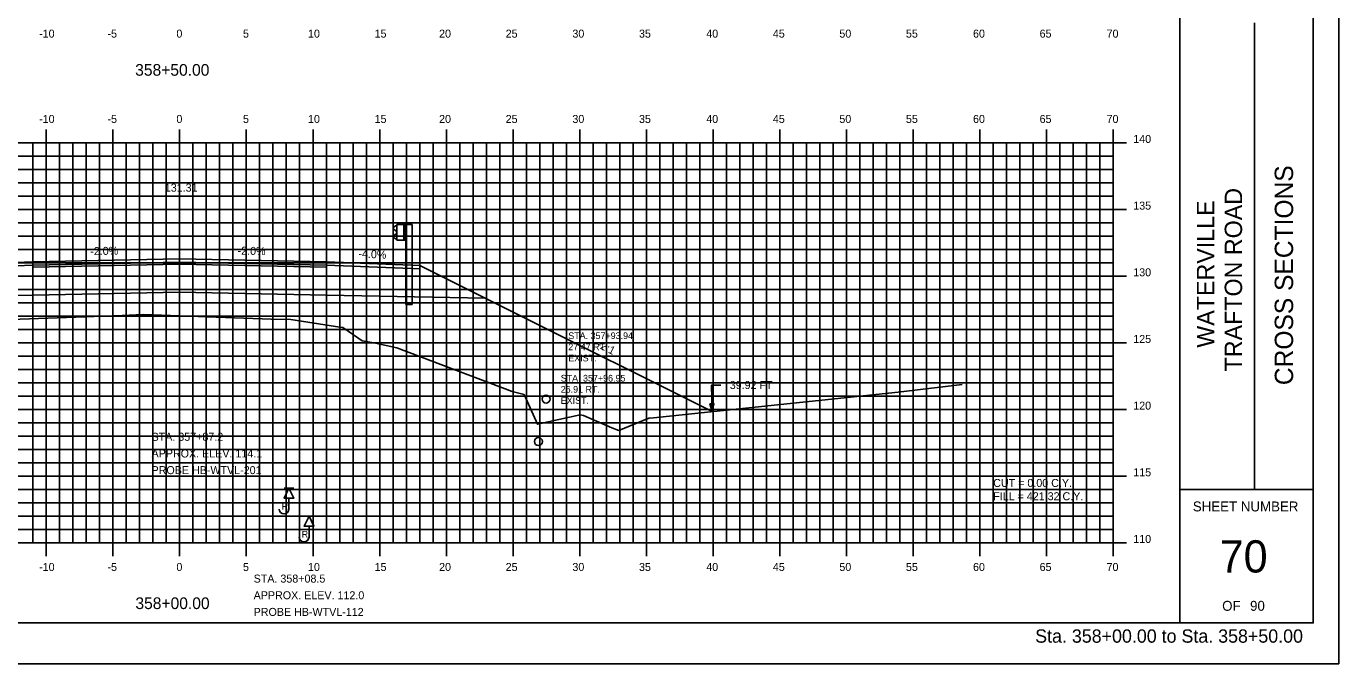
# Model space of a CAD drawing. Extents: x 1146081 to 1146251, y 608981 to 609091.
# Drawn here: x 1146152.7 to 1146251.1, y 608981.3 to 609029.1 of the extents above; entities that cross this region are included whole.
import ezdxf

# ---------------------------------------------------------------- set-up
doc = ezdxf.new("R2010")
doc.units = 0
for name, color, linetype in [('ANNOTATION', 7, 'Continuous'), ('BORDER', 7, 'Continuous'), ('D_Guardrail_Beam_Rt', 7, 'Continuous'), ('D_Guardrail_ConcBarrier', 7, 'Continuous'), ('D_Roadway_Centerline', 7, 'Continuous'), ('D_Roadway_Centerline_Text', 7, 'Continuous'), ('D_Roadway_Edge_Shoulder', 7, 'Continuous'), ('D_Roadway_Edge_TW', 7, 'Continuous'), ('D_Roadway_Pavement', 7, 'Continuous'), ('D_Roadway_SlopeLines', 7, 'Continuous'), ('D_Roadway_SubGrade', 7, 'Continuous'), ('D_Text_Monospaced', 7, 'Continuous'), ('D_Text_Standard', 7, 'Continuous'), ('H_V ANNOTATION', 7, 'Continuous'), ('HIGHWAY_TITLE', 7, 'Continuous'), ('MAJOR', 7, 'Continuous'), ('MINOR', 7, 'Continuous'), ('PLOT BOUNDARY', 7, 'Continuous'), ('ROCKS', 7, 'Continuous'), ('S_Drainage_Invert', 7, 'Continuous'), ('S_Roadway_Centerline', 7, 'Continuous')]:
    doc.layers.add(name, color=color, linetype=linetype)

msp = doc.modelspace()

# ---------------------------------------------------------------- linework, layer by layer
msp.add_lwpolyline([(1146119.749, 608997.946), (1146139.24, 609007.691), (1146141.24, 609008.691), (1146146.157, 609011.15), (1146146.158, 609011.15), (1146153.158, 609011.43), (1146164.158, 609011.65), (1146175.158, 609011.43), (1146182.158, 609011.15), (1146187.075, 609008.692), (1146189.075, 609007.692), (1146204.079, 609000.19)])
at = {"layer": 'BORDER'}
for p, q in [((1146239.158, 608984.335), (1146239.158, 609089.335)), ((1146244.749, 608994.338), (1146244.749, 609029.338)), ((1146239.158, 608994.338), (1146249.158, 608994.338))]:
    msp.add_line(p, q, dxfattribs=at)
msp.add_lwpolyline([(1146089.158, 608984.335), (1146249.158, 608984.335), (1146249.158, 609089.335), (1146089.158, 609089.335)], close=True, dxfattribs=at)
at = {"layer": 'D_Guardrail_Beam_Rt'}
for p, q in [((1146180.35, 609014.11), (1146180.207, 609014.01)), ((1146180.207, 609013.867), (1146180.402, 609013.731)), ((1146180.402, 609013.532), (1146180.207, 609013.396)), ((1146180.44, 609014.131), (1146180.366, 609014.117)), ((1146180.436, 609013.666), (1146180.436, 609013.596)), ((1146180.207, 609013.252), (1146180.35, 609013.152)), ((1146180.366, 609013.146), (1146180.44, 609013.131))]:
    msp.add_line(p, q, dxfattribs=at)
for centre, major_axis, start_param, end_param in [((1146180.257, 609013.938), (-0.0877, 0), 5.323254, 7.243116), ((1146180.374, 609014.076), (-0.0417, 0), 4.907132, 5.323254), ((1146180.357, 609013.666), (0.0789, 0), 0, 0.959931), ((1146180.357, 609013.596), (0.0789, 0), 5.323254, 6.283185), ((1146180.257, 609013.324), (-0.0877, 0), 5.323254, 7.243116), ((1146180.374, 609013.186), (-0.0417, 0), 0.959931, 1.376053)]:
    msp.add_ellipse(centre, major_axis=major_axis, ratio=0.995501, start_param=start_param, end_param=end_param, dxfattribs=at)
at = {"layer": 'D_Guardrail_ConcBarrier'}
for p, q in [((1146180.44, 609014.215), (1146181.127, 609014.215)), ((1146180.44, 609013.048), (1146180.44, 609014.215)), ((1146180.961, 609014.215), (1146180.961, 609013.048)), ((1146181.065, 609014.215), (1146181.065, 609013.048)), ((1146181.127, 609014.215), (1146181.598, 609014.215)), ((1146181.127, 609014.215), (1146181.127, 609013.048)), ((1146181.598, 609014.215), (1146181.598, 609008.215)), ((1146181.127, 609013.048), (1146180.44, 609013.048)), ((1146181.107, 609008.215), (1146181.107, 609013.048)), ((1146181.107, 609008.215), (1146181.598, 609008.215))]:
    msp.add_line(p, q, dxfattribs=at)
at = {"layer": 'D_Roadway_Edge_Shoulder'}
for points in [[(1146153.158, 609011.43), (1146146.158, 609011.15), (1146146.158, 609010.9), (1146153.158, 609011.18)], [(1146175.158, 609011.43), (1146182.158, 609011.15), (1146182.158, 609010.9), (1146175.158, 609011.18)]]:
    msp.add_lwpolyline(points, close=True, dxfattribs=at)
at = {"layer": 'D_Roadway_Edge_TW'}
msp.add_lwpolyline([(1146153.158, 609011.18), (1146153.158, 609011.43), (1146164.158, 609011.65), (1146175.158, 609011.43), (1146175.158, 609011.18), (1146164.158, 609011.4)], close=True, dxfattribs=at)
at = {"layer": 'D_Roadway_Pavement'}
msp.add_lwpolyline([(1146153.158, 609011.013), (1146153.158, 609011.18), (1146164.158, 609011.4), (1146175.158, 609011.18), (1146175.158, 609011.013), (1146164.158, 609011.233)], close=True, dxfattribs=at)
at = {"layer": 'D_Roadway_SlopeLines'}
for points in [[(1146187.075, 609008.692), (1146189.075, 609007.692)], [(1146189.075, 609007.692), (1146204.079, 609000.19)]]:
    msp.add_lwpolyline(points, dxfattribs=at)
at = {"layer": 'D_Roadway_SubGrade'}
for points in [[(1146153.158, 609011.013), (1146153.158, 609011.18), (1146146.158, 609010.9), (1146146.158, 609011.15), (1146146.157, 609011.15), (1146141.24, 609008.691), (1146153.158, 609008.93)], [(1146153.158, 609008.93), (1146153.158, 609011.013), (1146164.158, 609011.233), (1146175.158, 609011.013), (1146175.158, 609008.93), (1146164.158, 609009.15)], [(1146175.158, 609011.013), (1146175.158, 609011.18), (1146182.158, 609010.9), (1146182.158, 609011.15), (1146182.158, 609011.15), (1146187.075, 609008.692), (1146175.158, 609008.93)]]:
    msp.add_lwpolyline(points, close=True, dxfattribs=at)
at = {"layer": 'D_Text_Standard'}
msp.add_lwpolyline([(1146204.079, 609000.19), (1146204.045, 609002.18), (1146204.725, 609002.18)], dxfattribs=at)
msp.add_lwpolyline([(1146204.079, 609000.19), (1146203.923, 609000.769), (1146204.214, 609000.774)], close=True, dxfattribs=at)
at = {"layer": 'MAJOR'}
for p, q in [((1146154.158, 609021.337), (1146154.158, 609020.335)), ((1146159.158, 609021.337), (1146159.158, 609020.335)), ((1146164.158, 609021.337), (1146164.158, 609020.335)), ((1146169.158, 609021.337), (1146169.158, 609020.335)), ((1146174.158, 609021.337), (1146174.158, 609020.335)), ((1146179.158, 609021.337), (1146179.158, 609020.335)), ((1146184.158, 609021.337), (1146184.158, 609020.335)), ((1146189.158, 609021.337), (1146189.158, 609020.335)), ((1146194.158, 609021.337), (1146194.158, 609020.335)), ((1146199.158, 609021.337), (1146199.158, 609020.335)), ((1146204.158, 609021.337), (1146204.158, 609020.335)), ((1146209.158, 609021.337), (1146209.158, 609020.335)), ((1146214.158, 609021.337), (1146214.158, 609020.335)), ((1146219.158, 609021.337), (1146219.158, 609020.335)), ((1146224.158, 609021.337), (1146224.158, 609020.335)), ((1146229.158, 609021.337), (1146229.158, 609020.335)), ((1146234.158, 609021.337), (1146234.158, 609020.335)), ((1146094.158, 609020.335), (1146234.158, 609020.335)), ((1146094.158, 609020.335), (1146234.158, 609020.335)), ((1146154.158, 608990.335), (1146154.158, 609020.335)), ((1146159.158, 608990.335), (1146159.158, 609020.335)), ((1146164.158, 608990.335), (1146164.158, 609020.335)), ((1146169.158, 608990.335), (1146169.158, 609020.335)), ((1146174.158, 608990.335), (1146174.158, 609020.335)), ((1146179.158, 608990.335), (1146179.158, 609020.335)), ((1146184.158, 608990.335), (1146184.158, 609020.335)), ((1146189.158, 608990.335), (1146189.158, 609020.335)), ((1146194.158, 608990.335), (1146194.158, 609020.335)), ((1146199.158, 608990.335), (1146199.158, 609020.335)), ((1146204.158, 608990.335), (1146204.158, 609020.335)), ((1146209.158, 608990.335), (1146209.158, 609020.335)), ((1146214.158, 608990.335), (1146214.158, 609020.335)), ((1146219.158, 608990.335), (1146219.158, 609020.335)), ((1146224.158, 608990.335), (1146224.158, 609020.335)), ((1146229.158, 608990.335), (1146229.158, 609020.335)), ((1146235.16, 609020.335), (1146233.156, 609020.335)), ((1146234.158, 608990.335), (1146234.158, 609020.335)), ((1146234.158, 608990.335), (1146234.158, 609020.335)), ((1146094.158, 609015.335), (1146234.158, 609015.335)), ((1146235.16, 609015.335), (1146233.156, 609015.335)), ((1146094.158, 609010.335), (1146234.158, 609010.335)), ((1146235.16, 609010.335), (1146233.156, 609010.335)), ((1146094.158, 609005.335), (1146234.158, 609005.335)), ((1146235.16, 609005.335), (1146233.156, 609005.335)), ((1146094.158, 609000.335), (1146234.158, 609000.335)), ((1146235.16, 609000.335), (1146233.156, 609000.335)), ((1146094.158, 608995.335), (1146234.158, 608995.335)), ((1146235.16, 608995.335), (1146233.156, 608995.335)), ((1146094.158, 608990.335), (1146234.158, 608990.335)), ((1146094.158, 608990.335), (1146234.158, 608990.335)), ((1146154.158, 608989.333), (1146154.158, 608990.335)), ((1146159.158, 608989.333), (1146159.158, 608990.335)), ((1146164.158, 608989.333), (1146164.158, 608990.335)), ((1146169.158, 608989.333), (1146169.158, 608990.335)), ((1146174.158, 608989.333), (1146174.158, 608990.335)), ((1146179.158, 608989.333), (1146179.158, 608990.335)), ((1146184.158, 608989.333), (1146184.158, 608990.335)), ((1146189.158, 608989.333), (1146189.158, 608990.335)), ((1146194.158, 608989.333), (1146194.158, 608990.335)), ((1146199.158, 608989.333), (1146199.158, 608990.335)), ((1146204.158, 608989.333), (1146204.158, 608990.335)), ((1146209.158, 608989.333), (1146209.158, 608990.335)), ((1146214.158, 608989.333), (1146214.158, 608990.335)), ((1146219.158, 608989.333), (1146219.158, 608990.335)), ((1146224.158, 608989.333), (1146224.158, 608990.335)), ((1146229.158, 608989.333), (1146229.158, 608990.335)), ((1146235.16, 608990.335), (1146233.156, 608990.335)), ((1146234.158, 608989.333), (1146234.158, 608990.335))]:
    msp.add_line(p, q, dxfattribs=at)
at = {"layer": 'MINOR'}
for p, q in [((1146153.158, 608990.335), (1146153.158, 609020.335)), ((1146155.158, 608990.335), (1146155.158, 609020.335)), ((1146156.158, 608990.335), (1146156.158, 609020.335)), ((1146157.158, 608990.335), (1146157.158, 609020.335)), ((1146158.158, 608990.335), (1146158.158, 609020.335)), ((1146160.158, 608990.335), (1146160.158, 609020.335)), ((1146161.158, 608990.335), (1146161.158, 609020.335)), ((1146162.158, 608990.335), (1146162.158, 609020.335)), ((1146163.158, 608990.335), (1146163.158, 609020.335)), ((1146165.158, 608990.335), (1146165.158, 609020.335)), ((1146166.158, 608990.335), (1146166.158, 609020.335)), ((1146167.158, 608990.335), (1146167.158, 609020.335)), ((1146168.158, 608990.335), (1146168.158, 609020.335)), ((1146170.158, 608990.335), (1146170.158, 609020.335)), ((1146171.158, 608990.335), (1146171.158, 609020.335)), ((1146172.158, 608990.335), (1146172.158, 609020.335)), ((1146173.158, 608990.335), (1146173.158, 609020.335)), ((1146175.158, 608990.335), (1146175.158, 609020.335)), ((1146176.158, 608990.335), (1146176.158, 609020.335)), ((1146177.158, 608990.335), (1146177.158, 609020.335)), ((1146178.158, 608990.335), (1146178.158, 609020.335)), ((1146180.158, 608990.335), (1146180.158, 609020.335)), ((1146181.158, 608990.335), (1146181.158, 609020.335)), ((1146182.158, 608990.335), (1146182.158, 609020.335)), ((1146183.158, 608990.335), (1146183.158, 609020.335)), ((1146185.158, 608990.335), (1146185.158, 609020.335)), ((1146186.158, 608990.335), (1146186.158, 609020.335)), ((1146187.158, 608990.335), (1146187.158, 609020.335)), ((1146188.158, 608990.335), (1146188.158, 609020.335)), ((1146190.158, 608990.335), (1146190.158, 609020.335)), ((1146191.158, 608990.335), (1146191.158, 609020.335)), ((1146192.158, 608990.335), (1146192.158, 609020.335)), ((1146193.158, 608990.335), (1146193.158, 609020.335)), ((1146195.158, 608990.335), (1146195.158, 609020.335)), ((1146196.158, 608990.335), (1146196.158, 609020.335)), ((1146197.158, 608990.335), (1146197.158, 609020.335)), ((1146198.158, 608990.335), (1146198.158, 609020.335)), ((1146200.158, 608990.335), (1146200.158, 609020.335)), ((1146201.158, 608990.335), (1146201.158, 609020.335)), ((1146202.158, 608990.335), (1146202.158, 609020.335)), ((1146203.158, 608990.335), (1146203.158, 609020.335)), ((1146205.158, 608990.335), (1146205.158, 609020.335)), ((1146206.158, 608990.335), (1146206.158, 609020.335)), ((1146207.158, 608990.335), (1146207.158, 609020.335)), ((1146208.158, 608990.335), (1146208.158, 609020.335)), ((1146210.158, 608990.335), (1146210.158, 609020.335)), ((1146211.158, 608990.335), (1146211.158, 609020.335)), ((1146212.158, 608990.335), (1146212.158, 609020.335)), ((1146213.158, 608990.335), (1146213.158, 609020.335)), ((1146215.158, 608990.335), (1146215.158, 609020.335)), ((1146216.158, 608990.335), (1146216.158, 609020.335)), ((1146217.158, 608990.335), (1146217.158, 609020.335)), ((1146218.158, 608990.335), (1146218.158, 609020.335)), ((1146220.158, 608990.335), (1146220.158, 609020.335)), ((1146221.158, 608990.335), (1146221.158, 609020.335)), ((1146222.158, 608990.335), (1146222.158, 609020.335)), ((1146223.158, 608990.335), (1146223.158, 609020.335)), ((1146225.158, 608990.335), (1146225.158, 609020.335)), ((1146226.158, 608990.335), (1146226.158, 609020.335)), ((1146227.158, 608990.335), (1146227.158, 609020.335)), ((1146228.158, 608990.335), (1146228.158, 609020.335)), ((1146230.158, 608990.335), (1146230.158, 609020.335)), ((1146231.158, 608990.335), (1146231.158, 609020.335)), ((1146232.158, 608990.335), (1146232.158, 609020.335)), ((1146233.158, 608990.335), (1146233.158, 609020.335)), ((1146094.158, 609019.335), (1146234.158, 609019.335)), ((1146234.158, 609019.335), (1146233.156, 609019.335)), ((1146094.158, 609018.335), (1146234.158, 609018.335)), ((1146234.158, 609018.335), (1146233.156, 609018.335)), ((1146094.158, 609017.335), (1146234.158, 609017.335)), ((1146234.158, 609017.335), (1146233.156, 609017.335)), ((1146094.158, 609016.335), (1146234.158, 609016.335)), ((1146234.158, 609016.335), (1146233.156, 609016.335)), ((1146094.158, 609014.335), (1146234.158, 609014.335)), ((1146234.158, 609014.335), (1146233.156, 609014.335)), ((1146094.158, 609013.335), (1146234.158, 609013.335)), ((1146234.158, 609013.335), (1146233.156, 609013.335)), ((1146094.158, 609012.335), (1146234.158, 609012.335)), ((1146234.158, 609012.335), (1146233.156, 609012.335)), ((1146094.158, 609011.335), (1146234.158, 609011.335)), ((1146234.158, 609011.335), (1146233.156, 609011.335)), ((1146094.158, 609009.335), (1146234.158, 609009.335)), ((1146234.158, 609009.335), (1146233.156, 609009.335)), ((1146094.158, 609008.335), (1146234.158, 609008.335)), ((1146234.158, 609008.335), (1146233.156, 609008.335)), ((1146094.158, 609007.335), (1146234.158, 609007.335)), ((1146234.158, 609007.335), (1146233.156, 609007.335)), ((1146094.158, 609006.335), (1146234.158, 609006.335)), ((1146234.158, 609006.335), (1146233.156, 609006.335)), ((1146094.158, 609004.335), (1146234.158, 609004.335)), ((1146234.158, 609004.335), (1146233.156, 609004.335)), ((1146094.158, 609003.335), (1146234.158, 609003.335)), ((1146234.158, 609003.335), (1146233.156, 609003.335)), ((1146094.158, 609002.335), (1146234.158, 609002.335)), ((1146234.158, 609002.335), (1146233.156, 609002.335)), ((1146094.158, 609001.335), (1146234.158, 609001.335)), ((1146234.158, 609001.335), (1146233.156, 609001.335)), ((1146094.158, 608999.335), (1146234.158, 608999.335)), ((1146234.158, 608999.335), (1146233.156, 608999.335)), ((1146094.158, 608998.335), (1146234.158, 608998.335)), ((1146234.158, 608998.335), (1146233.156, 608998.335)), ((1146094.158, 608997.335), (1146234.158, 608997.335)), ((1146234.158, 608997.335), (1146233.156, 608997.335)), ((1146094.158, 608996.335), (1146234.158, 608996.335)), ((1146234.158, 608996.335), (1146233.156, 608996.335)), ((1146094.158, 608994.335), (1146234.158, 608994.335)), ((1146234.158, 608994.335), (1146233.156, 608994.335)), ((1146094.158, 608993.335), (1146234.158, 608993.335)), ((1146234.158, 608993.335), (1146233.156, 608993.335)), ((1146094.158, 608992.335), (1146234.158, 608992.335)), ((1146234.158, 608992.335), (1146233.156, 608992.335)), ((1146094.158, 608991.335), (1146234.158, 608991.335)), ((1146234.158, 608991.335), (1146233.156, 608991.335))]:
    msp.add_line(p, q, dxfattribs=at)
at = {"layer": 'PLOT BOUNDARY'}
msp.add_lwpolyline([(1146081.065, 608981.276), (1146251.065, 608981.276), (1146251.065, 609091.276), (1146081.065, 609091.276)], close=True, dxfattribs=at)
at = {"layer": 'ROCKS'}
for p, q in [((1146172.727, 608994.435), (1146171.989, 608994.435)), ((1146172.358, 608993.697), (1146172.358, 608992.882)), ((1146174.227, 608992.335), (1146173.489, 608992.335)), ((1146173.858, 608991.597), (1146173.858, 608990.782))]:
    msp.add_line(p, q, dxfattribs=at)
for points in [[(1146172.358, 608994.435), (1146172.727, 608993.697), (1146171.989, 608993.697)], [(1146173.858, 608992.335), (1146174.227, 608991.597), (1146173.489, 608991.597)]]:
    msp.add_lwpolyline(points, close=True, dxfattribs=at)
for centre in [(1146171.985, 608992.882), (1146173.485, 608990.782)]:
    msp.add_arc(centre, 0.373, 180, 0, dxfattribs=at)
at = {"layer": 'S_Drainage_Invert'}
for centre in [(1146191.632, 609001.129), (1146191.064, 608997.944)]:
    msp.add_circle(centre, 0.3, dxfattribs=at)
at = {"layer": 'S_Roadway_Centerline'}
msp.add_lwpolyline([(1146150.798, 609007.066), (1146159.846, 609007.401), (1146161.432, 609007.464), (1146171.01, 609007.121), (1146172.487, 609007.085), (1146175.847, 609006.568), (1146176.385, 609006.506), (1146177.841, 609005.488), (1146178.841, 609005.331), (1146180.447, 609004.962), (1146189.096, 609001.7), (1146189.983, 609001.469), (1146191.002, 608999.24), (1146194.178, 608999.938), (1146194.441, 608999.898), (1146196.553, 608998.968), (1146197.09, 608998.777), (1146199.348, 608999.689), (1146199.382, 608999.703), (1146199.69, 608999.732), (1146218.043, 609001.646), (1146222.835, 609002.21)], dxfattribs=at)

# ---------------------------------------------------------------- texts
at = {"layer": 'ANNOTATION'}
for s, rotation, p in [('-2.0%', 1.14576, (1146157.461, 609011.916)), ('-2.0%', 358.85424, (1146168.501, 609011.963)), ('-4.0%', 357.70939, (1146177.554, 609011.735)), ('-2:1', 333.43495, (1146195.4, 609005.047))]:
    msp.add_text(s, height=0.6, rotation=rotation, dxfattribs=at).set_placement(p)
at = {"layer": 'BORDER'}
msp.add_text('CROSS SECTIONS', height=1.37787, rotation=90, dxfattribs=at).set_placement((1146247.643, 609002.172))
for s, height, p in [('SHEET NUMBER', 0.74527, (1146240.124, 608992.701)), ('70', 2.4194, (1146242.134, 608988.118)), ('OF', 0.7453, (1146242.325, 608985.248)), ('90', 0.7453, (1146244.415, 608985.248))]:
    msp.add_text(s, height=height, dxfattribs=at).set_placement(p)
at = {"layer": 'D_Roadway_Centerline'}
for s, p in [('C', (1146164.153, 609011.65)), ('L', (1146164.158, 609011.643))]:
    msp.add_text(s, height=0.0146, dxfattribs=at).set_placement(p)
at = {"layer": 'D_Roadway_Centerline_Text'}
msp.add_text('131.31', height=0.6, dxfattribs=at).set_placement((1146163.045, 609016.682))
at = {"layer": 'D_Text_Monospaced'}
for s, height, p in [('STA. 357+93.94', 0.49998, (1146193.299, 609005.627)), ('27.47 RT.', 0.5, (1146193.299, 609004.793)), ('EXIST. ', 0.5, (1146193.299, 609003.953)), ('STA. 357+96.95', 0.49998, (1146192.731, 609002.442)), ('26.91 RT.', 0.5, (1146192.731, 609001.608)), ('EXIST. ', 0.5, (1146192.731, 609000.768))]:
    msp.add_text(s, height=height, dxfattribs=at).set_placement(p)
at = {"layer": 'D_Text_Standard'}
for s, p in [('39.92 FT', (1146205.405, 609001.88)), ('CUT = 0.00 C.Y.', (1146225.158, 608994.535)), ('FILL = 421.32 C.Y.', (1146225.158, 608993.539))]:
    msp.add_text(s, height=0.6, dxfattribs=at).set_placement(p)
at = {"layer": 'H_V ANNOTATION'}
for s, height, p in [('-10', 0.6, (1146153.623, 609028.235)), ('-5', 0.6, (1146158.749, 609028.235)), ('0', 0.6, (1146163.917, 609028.235)), ('5', 0.6, (1146168.909, 609028.235)), ('10', 0.6, (1146173.784, 609028.235)), ('15', 0.6, (1146178.776, 609028.235)), ('20', 0.6, (1146183.612, 609028.235)), ('25', 0.6, (1146188.604, 609028.235)), ('30', 0.6, (1146193.607, 609028.235)), ('35', 0.6, (1146198.599, 609028.235)), ('40', 0.6, (1146203.644, 609028.235)), ('45', 0.6, (1146208.636, 609028.235)), ('50', 0.6, (1146213.623, 609028.235)), ('55', 0.6, (1146218.615, 609028.235)), ('60', 0.6, (1146223.644, 609028.235)), ('65', 0.6, (1146228.636, 609028.235)), ('70', 0.6, (1146233.66, 609028.235)), ('358+50.00', 0.875, (1146160.826, 609025.378)), ('-10', 0.6, (1146153.623, 609021.835)), ('-5', 0.6, (1146158.749, 609021.835)), ('0', 0.6, (1146163.917, 609021.835)), ('5', 0.6, (1146168.909, 609021.835)), ('10', 0.6, (1146173.784, 609021.835)), ('15', 0.6, (1146178.776, 609021.835)), ('20', 0.6, (1146183.612, 609021.835)), ('25', 0.6, (1146188.604, 609021.835)), ('30', 0.6, (1146193.607, 609021.835)), ('35', 0.6, (1146198.599, 609021.835)), ('40', 0.6, (1146203.644, 609021.835)), ('45', 0.6, (1146208.636, 609021.835)), ('50', 0.6, (1146213.623, 609021.835)), ('55', 0.6, (1146218.615, 609021.835)), ('60', 0.6, (1146223.644, 609021.835)), ('65', 0.6, (1146228.636, 609021.835)), ('70', 0.6, (1146233.66, 609021.835)), ('140', 0.6, (1146235.658, 609020.335)), ('135', 0.6, (1146235.658, 609015.335)), ('130', 0.6, (1146235.658, 609010.335)), ('125', 0.6, (1146235.658, 609005.335)), ('120', 0.6, (1146235.658, 609000.335)), ('115', 0.6, (1146235.658, 608995.335)), ('110', 0.6, (1146235.658, 608990.335)), ('-10', 0.6, (1146153.623, 608988.235)), ('-5', 0.6, (1146158.749, 608988.235)), ('0', 0.6, (1146163.917, 608988.235)), ('5', 0.6, (1146168.909, 608988.235)), ('10', 0.6, (1146173.784, 608988.235)), ('15', 0.6, (1146178.776, 608988.235)), ('20', 0.6, (1146183.612, 608988.235)), ('25', 0.6, (1146188.604, 608988.235)), ('30', 0.6, (1146193.607, 608988.235)), ('35', 0.6, (1146198.599, 608988.235)), ('40', 0.6, (1146203.644, 608988.235)), ('45', 0.6, (1146208.636, 608988.235)), ('50', 0.6, (1146213.623, 608988.235)), ('55', 0.6, (1146218.615, 608988.235)), ('60', 0.6, (1146223.644, 608988.235)), ('65', 0.6, (1146228.636, 608988.235)), ('70', 0.6, (1146233.66, 608988.235)), ('358+00.00', 0.875, (1146160.842, 608985.378)), ('Sta. 358+00.00 to Sta. 358+50.00', 1.0002, (1146228.304, 608982.855))]:
    msp.add_text(s, height=height, dxfattribs=at).set_placement(p)
at = {"layer": 'HIGHWAY_TITLE'}
for s, height, p in [('TRAFTON ROAD', 1.30428, (1146243.818, 609003.201)), ('WATERVILLE', 1.3043, (1146241.731, 609004.98))]:
    msp.add_text(s, height=height, rotation=90, dxfattribs=at).set_placement(p)
at = {"layer": 'ROCKS'}
for s, p in [('STA. 357+87.2', (1146162.053, 608997.998)), ('APPROX. ELEV. 114.1', (1146162.053, 608996.748)), ('PROBE HB-WTVL-201', (1146162.053, 608995.498)), ('STA. 358+08.5', (1146169.708, 608987.363)), ('APPROX. ELEV. 112.0', (1146169.708, 608986.113)), ('PROBE HB-WTVL-112', (1146169.708, 608984.863))]:
    msp.add_text(s, height=0.6, rotation=360, dxfattribs=at).set_placement(p)
for p in [(1146171.813, 608992.839), (1146173.313, 608990.739)]:
    msp.add_text('R', height=0.492, dxfattribs=at).set_placement(p)
at = {"layer": 'S_Roadway_Centerline'}
for s, p in [('L', (1146161.423, 609007.457)), ('C', (1146161.426, 609007.464))]:
    msp.add_text(s, height=0.0146, dxfattribs=at).set_placement(p)

doc.saveas('drawing.dxf')
